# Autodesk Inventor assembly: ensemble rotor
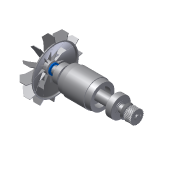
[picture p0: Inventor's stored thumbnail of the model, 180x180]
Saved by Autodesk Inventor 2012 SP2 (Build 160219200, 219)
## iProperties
Created: 2013-04
Part Number: ensemble rotor
Document SubType Name: Assembly
Designer: papa
Mass: 309.061 g
Surface Area: 1137 cm^2
Volume: 309.061 cm^3
Density: 1 g/cm^3
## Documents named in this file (14)
- F:\Consmec\TBPMSMA\CCF\01-CCF Cermex Moteur\01-02 Dossier Rerssources CERMEX\02-01-04 - Dessins Cermex\02-01-04-01- Dessins 3D Cermex\02-01-04-01-01 - Dessins 3D Motoreducteur\02-01-04-01-01-01 - Composants 3D Motoreducteur R43\ensemble rotor.iam
- F:\Consmec\TBPMSMA\CCF\01-CCF Cermex Moteur\01-02 Dossier Rerssources CERMEX\02-01-04 - Dessins Cermex\02-01-04-01- Dessins 3D Cermex\02-01-04-01-01 - Dessins 3D Motoreducteur\02-01-04-01-01-01 - Composants 3D Motoreducteur R43\rotor.ipt
- F:\Consmec\TBPMSMA\CCF\01-CCF Cermex Moteur\01-02 Dossier Rerssources CERMEX\02-01-04 - Dessins Cermex\02-01-04-01- Dessins 3D Cermex\02-01-04-01-01 - Dessins 3D Motoreducteur\02-01-04-01-01-01 - Composants 3D Motoreducteur R43\roulement 6303Z.ipt
- F:\Consmec\TBPMSMA\CCF\01-CCF Cermex Moteur\01-02 Dossier Rerssources CERMEX\02-01-04 - Dessins Cermex\02-01-04-01- Dessins 3D Cermex\02-01-04-01-01 - Dessins 3D Motoreducteur\02-01-04-01-01-01 - Composants 3D Motoreducteur R43\roulement 6203DU.ipt
- F:\Consmec\TBPMSMA\CCF\01-CCF Cermex Moteur\01-02 Dossier Rerssources CERMEX\02-01-04 - Dessins Cermex\02-01-04-01- Dessins 3D Cermex\02-01-04-01-01 - Dessins 3D Motoreducteur\02-01-04-01-01-01 - Composants 3D Motoreducteur R43\clavette _5_5_18.ipt
- F:\Consmec\TBPMSMA\CCF\01-CCF Cermex Moteur\01-02 Dossier Rerssources CERMEX\02-01-04 - Dessins Cermex\02-01-04-01- Dessins 3D Cermex\02-01-04-01-01 - Dessins 3D Motoreducteur\02-01-04-01-01-01 - Composants 3D Motoreducteur R43\clavette _2_2_12.ipt
- F:\Consmec\TBPMSMA\CCF\01-CCF Cermex Moteur\01-02 Dossier Rerssources CERMEX\02-01-04 - Dessins Cermex\02-01-04-01- Dessins 3D Cermex\02-01-04-01-01 - Dessins 3D Motoreducteur\02-01-04-01-01-01 - Composants 3D Motoreducteur R43\25 - Pignon entree -  Z27.ipt
- F:\Consmec\TBPMSMA\CCF\01-CCF Cermex Moteur\01-02 Dossier Rerssources CERMEX\02-01-04 - Dessins Cermex\02-01-04-01- Dessins 3D Cermex\02-01-04-01-01 - Dessins 3D Motoreducteur\02-01-04-01-01-01 - Composants 3D Motoreducteur R43\ventilateur.ipt
- F:\Consmec\TBPMSMA\CCF\01-CCF Cermex Moteur\01-02 Dossier Rerssources CERMEX\02-01-04 - Dessins Cermex\02-01-04-01- Dessins 3D Cermex\02-01-04-01-01 - Dessins 3D Motoreducteur\02-01-04-01-01-01 - Composants 3D Motoreducteur R43\anneau elastique 10 x 1.ipt
- F:\Consmec\TBPMSMA\CCF\01-CCF Cermex Moteur\01-02 Dossier Rerssources CERMEX\02-01-04 - Dessins Cermex\02-01-04-01- Dessins 3D Cermex\02-01-04-01-01 - Dessins 3D Motoreducteur\02-01-04-01-01-01 - Composants 3D Motoreducteur R43\anneau elastique 15 x 1.ipt
- F:\Consmec\TBPMSMA\CCF\01-CCF Cermex Moteur\01-02 Dossier Rerssources CERMEX\02-01-04 - Dessins Cermex\02-01-04-01- Dessins 3D Cermex\02-01-04-01-01 - Dessins 3D Motoreducteur\02-01-04-01-01-01 - Composants 3D Motoreducteur R43\anneau elastique 17 x 1.ipt
- F:\Consmec\TBPMSMA\CCF\01-CCF Cermex Moteur\01-02 Dossier Rerssources CERMEX\02-01-04 - Dessins Cermex\02-01-04-01- Dessins 3D Cermex\02-01-04-01-01 - Dessins 3D Motoreducteur\02-01-04-01-01-01 - Composants 3D Motoreducteur R43\flasque roulement.ipt
- F:\Consmec\TBPMSMA\CCF\01-CCF Cermex Moteur\01-02 Dossier Rerssources CERMEX\02-01-04 - Dessins Cermex\02-01-04-01- Dessins 3D Cermex\02-01-04-01-01 - Dessins 3D Motoreducteur\02-01-04-01-01-01 - Composants 3D Motoreducteur R43\deflecteur.ipt
- F:\Consmec\TBPMSMA\CCF\01-CCF Cermex Moteur\01-02 Dossier Rerssources CERMEX\02-01-04 - Dessins Cermex\02-01-04-01- Dessins 3D Cermex\02-01-04-01-01 - Dessins 3D Motoreducteur\02-01-04-01-01-01 - Composants 3D Motoreducteur R43\Joint_Vring_17.ipt
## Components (13 placed, 13 different names)
1. rotor:1 — Logement:1, Logement:2, Logement:3, Logement:4, Logement:9, Logement:10, Logement:11, Logement:13, Logement:14, Logement:15, Logement:17
2. roulement 6303Z:1 — Logement:19, Logement:20
3. roulement 6203DU:1 — Logement:15
4. clavette _5_5_18:1 — Logement:9, Logement:10, Angle:1
5. clavette _2_2_12:1 — Logement:1, Logement:2
6. pignon entree:1 — Logement:3
7. ventilateur:1 — Logement:12, Angle:1
8. anneau elastique 10 x 1:1 — Logement:4
9. anneau elastique 15 x 1:1 — Logement:11, Logement:12
10. anneau elastique 17 x 1:1 — Logement:20
11. flasque roulement:1 — Logement:17, Logement:19
12. deflecteur:1 — Logement:14
13. Joint_Vring_17:1 — Logement:13
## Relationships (15: Insert 14, Angle 1)
- Logement:1 [Insert]: rotor:1 ↔ clavette _2_2_12:1
- Logement:2 [Insert]: rotor:1 ↔ clavette _2_2_12:1
- Logement:3 [Insert]: rotor:1 ↔ pignon entree:1
- Logement:4 [Insert]: rotor:1 ↔ anneau elastique 10 x 1:1
- Logement:9 [Insert]: rotor:1 ↔ clavette _5_5_18:1
- Logement:10 [Insert]: rotor:1 ↔ clavette _5_5_18:1
- Logement:11 [Insert]: rotor:1 ↔ anneau elastique 15 x 1:1
- Logement:12 [Insert]: ventilateur:1 ↔ anneau elastique 15 x 1:1
- Logement:13 [Insert]: rotor:1 ↔ Joint_Vring_17:1
- Logement:14 [Insert]: rotor:1 ↔ deflecteur:1
- Logement:15 [Insert]: rotor:1 ↔ roulement 6203DU:1
- Logement:17 [Insert]: rotor:1 ↔ flasque roulement:1
- Logement:19 [Insert]: roulement 6303Z:1 ↔ flasque roulement:1
- Logement:20 [Insert]: roulement 6303Z:1 ↔ anneau elastique 17 x 1:1
- Angle:1: clavette _5_5_18:1 ↔ ventilateur:1
